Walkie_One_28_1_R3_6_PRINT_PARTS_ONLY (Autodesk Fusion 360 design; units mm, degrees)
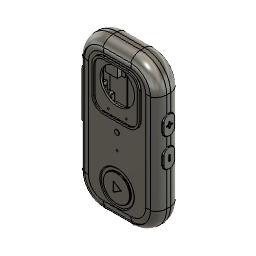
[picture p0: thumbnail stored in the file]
part number: 2026-09-15-14-07-18-350
part number: 2026-09-15-14-09-39-419
part number: 2026-09-15-14-09-41-943
part number: 2026-09-15-14-09-44-607
part number: 2026-09-15-14-09-47-211
part number: 2026-09-15-14-09-50-113
part number: 2026-09-15-15-14-47-004
part number: 2026-09-15-15-14-48-512
part number: 2026-09-15-15-14-49-986
part number: 2026-09-15-15-14-51-454
part number: 2026-09-15-15-14-52-894
part number: 2026-09-15-15-14-54-404
part number: 2026-09-15-15-14-55-869
part number: 2026-09-15-15-14-57-410
part number: 2026-09-15-15-14-58-963
part number: 2026-09-15-15-15-00-469
part number: 2026-09-15-15-15-01-966
part number: 2026-09-15-15-15-03-467
part number: 2026-09-15-15-15-04-938
part number: 2026-09-15-15-15-06-376
named bodies: "C28_R3_6_F01_Flexible_Rim", "C28_R3_6_F02_Flexible_Talk_Grip", "C28_R3_6_M04_Print_Grille_Bezel", "C28_R3_6_L01_Lens_Fit_Proxy", "C28_R3_6_L02_Light_Guide_Fit_Proxy", "C28_R3_6_P11_Lower_Speaker_Keeper", "C28_R3_6_P12_Upper_Speaker_Keeper", "C28_R3_6_P13_Microphone_Keeper", "C28_R3_6_P14_LED_Keeper", "C28_R3_6_P19_Battery_Keeper_1", "C28_R3_6_P20_Battery_Keeper_2", "C28_R3_6_P03_One_Piece_Play_Button", "C28_R3_6_P04_Front_Switch_Clamp", "C28_R3_6_P05_Talk_Carrier", "C28_R3_6_P06_One_Piece_Volume_Up", "C28_R3_6_P07_One_Piece_Volume_Down", "C28_R3_6_P08_Talk_Switch_Cradle", "C28_R3_6_P09_Volume_Up_Switch_Cradle", "C28_R3_6_P10_Volume_Down_Switch_Cradle", "C28_R3_6_P17_Lower_Talk_Guide", "C28_R3_6_P18_Upper_Talk_Guide", "C28_R3_6_K01_Volume_Up_Capture", "C28_R3_6_K02_Volume_Down_Capture", "C28_R3_6_P15_Lower_Antenna_Frame", "C28_R3_6_P16_Upper_Antenna_Frame", "C28_R3_6_P01_Front_Shell", "C28_R3_6_P02_Rear_Shell", "C28_R3_6_K03_Battery_Adapter_Cover"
